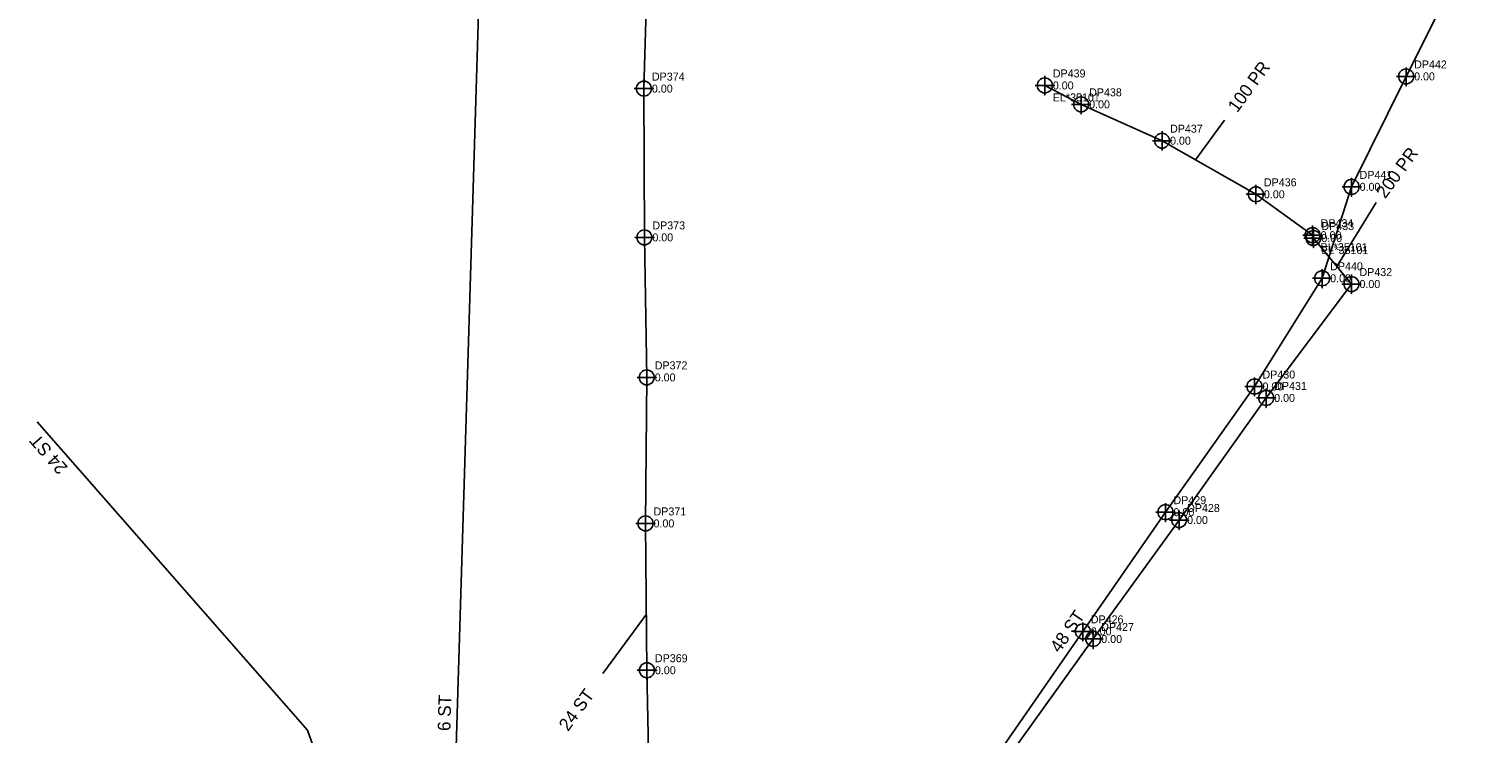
# Model space of a CAD drawing. Extents: x 1182504 to 1186036, y 573002 to 575111.
# Drawn here: x 1183688.1 to 1184140, y 573350.5 to 573570.7 of the extents above; entities that cross this region are included whole.
import ezdxf

# ---------------------------------------------------------------- set-up
doc = ezdxf.new("R2010")
doc.units = 0
for name, color, linetype in [('Exist Utilities Telephone UG Cable SUE LOS C', 7, 'Continuous'), ('Exist Utilities Telephone UG Cable SUE LOS C Cogo Comment', 7, 'Continuous'), ('Exist Utilities Telephone UG Cable SUE LOS C Cogo Elevation', 7, 'Continuous'), ('Exist Utilities Telephone UG Cable SUE LOS C Cogo Number', 7, 'Continuous'), ('Exist Utilities Telephone UG Cable SUE LOS C Cogo Point CELL', 7, 'Continuous'), ('Exist Utilities Telephone UG Cable SUE LOS C Leader', 7, 'Continuous'), ('Exist Utilities Telephone UG Cable SUE LOS C Text', 7, 'Continuous'), ('Exist Utilities Telephone UG Conduit SUE LOS B', 7, 'Continuous'), ('Exist Utilities Telephone UG Conduit SUE LOS B Cogo Elevation', 7, 'Continuous'), ('Exist Utilities Telephone UG Conduit SUE LOS B Cogo Number', 7, 'Continuous'), ('Exist Utilities Telephone UG Conduit SUE LOS B Cogo Point CELL', 7, 'Continuous'), ('Exist Utilities Telephone UG Conduit SUE LOS B Text', 7, 'Continuous'), ('Exist Utilities Telephone UG FO SUE LOS C', 7, 'Continuous'), ('Exist Utilities Telephone UG FO SUE LOS C Cogo Elevation', 7, 'Continuous'), ('Exist Utilities Telephone UG FO SUE LOS C Cogo Number', 7, 'Continuous'), ('Exist Utilities Telephone UG FO SUE LOS C Cogo Point CELL', 7, 'Continuous'), ('Exist Utilities Telephone UG FO SUE LOS C Leader', 7, 'Continuous'), ('Exist Utilities Telephone UG FO SUE LOS C Text', 7, 'Continuous')]:
    doc.layers.add(name, color=color, linetype=linetype)

msp = doc.modelspace()

# ---------------------------------------------------------------- linework, layer by layer
at = {"layer": 'Exist Utilities Telephone UG Cable SUE LOS C'}
for points in [[(1184089.19, 573506.18), (1184071.47, 573518.96), (1184042.14, 573535.72), (1184016.86, 573547.08), (1184005.51, 573552.99)], [(1183761.25, 573038.53), (1183769.09, 573034.41), (1183772.83, 573037.9), (1183792.84, 573062.44), (1183815.5, 573091.52), (1183842.15, 573128.3), (1183871.65, 573168.11), (1183894.45, 573200.64), (1183915.52, 573231.01), (1183941.95, 573268.28), (1183966.78, 573306.07), (1183979.43, 573323.54), (1183993.99, 573342.83), (1184020.65, 573379.96), (1184047.47, 573417.15), (1184074.68, 573455.3), (1184101.33, 573490.9), (1184089.43, 573505.28)]]:
    msp.add_lwpolyline(points, dxfattribs=at)
at = {"layer": 'Exist Utilities Telephone UG Cable SUE LOS C Cogo Point CELL'}
for points in [[(1184005.51, 573555.99), (1184005.51, 573549.99), (1184005.51, 573552.99), (1184008.51, 573552.99), (1184002.51, 573552.99)], [(1184016.86, 573550.08), (1184016.86, 573544.08), (1184016.86, 573547.08), (1184019.86, 573547.08), (1184013.86, 573547.08)], [(1184042.14, 573538.72), (1184042.14, 573532.72), (1184042.14, 573535.72), (1184045.14, 573535.72), (1184039.14, 573535.72)], [(1184071.47, 573521.96), (1184071.47, 573515.96), (1184071.47, 573518.96), (1184074.47, 573518.96), (1184068.47, 573518.96)], [(1184089.19, 573509.18), (1184089.19, 573503.18), (1184089.19, 573506.18), (1184092.19, 573506.18), (1184086.19, 573506.18)], [(1184089.43, 573508.28), (1184089.43, 573502.28), (1184089.43, 573505.28), (1184092.43, 573505.28), (1184086.43, 573505.28)], [(1184101.33, 573493.9), (1184101.33, 573487.9), (1184101.33, 573490.9), (1184104.33, 573490.9), (1184098.33, 573490.9)], [(1184074.68, 573458.3), (1184074.68, 573452.3), (1184074.68, 573455.3), (1184077.68, 573455.3), (1184071.68, 573455.3)], [(1184047.47, 573420.15), (1184047.47, 573414.15), (1184047.47, 573417.15), (1184050.47, 573417.15), (1184044.47, 573417.15)], [(1184020.65, 573382.96), (1184020.65, 573376.96), (1184020.65, 573379.96), (1184023.65, 573379.96), (1184017.65, 573379.96)]]:
    msp.add_lwpolyline(points, dxfattribs=at)
for centre in [(1184005.51, 573552.99), (1184016.86, 573547.08), (1184042.14, 573535.72), (1184071.47, 573518.96), (1184089.19, 573506.18), (1184089.43, 573505.28), (1184101.33, 573490.9), (1184074.68, 573455.3), (1184047.47, 573417.15), (1184020.65, 573379.96)]:
    msp.add_circle(centre, 2.34, dxfattribs=at)
at = {"layer": 'Exist Utilities Telephone UG Cable SUE LOS C Leader'}
for p, q in [((1184052.63, 573529.73), (1184061.7, 573542.18)), ((1184096.74, 573496.44), (1184109.1, 573516.44))]:
    msp.add_line(p, q, dxfattribs=at)
at = {"layer": 'Exist Utilities Telephone UG Conduit SUE LOS B'}
msp.add_lwpolyline([(1184020.78, 573306.4), (1183988.14, 573330.66), (1183985.98, 573336.24), (1183991.53, 573344.95), (1184017.37, 573382.34), (1184043.22, 573419.6), (1184071.03, 573458.88), (1184092.18, 573492.71), (1184101.38, 573521.29), (1184118.41, 573555.81), (1184137.37, 573593.76), (1184158.33, 573627.01), (1184186.36, 573674.25), (1184210.73, 573715)], dxfattribs=at)
at = {"layer": 'Exist Utilities Telephone UG Conduit SUE LOS B Cogo Point CELL'}
for points in [[(1184118.39, 573558.62), (1184118.42, 573552.81), (1184118.41, 573555.81), (1184121.42, 573555.81), (1184115.42, 573555.81)], [(1184101.36, 573524.1), (1184101.39, 573518.29), (1184101.38, 573521.29), (1184104.39, 573521.29), (1184098.39, 573521.29)], [(1184092.16, 573495.52), (1184092.19, 573489.71), (1184092.18, 573492.71), (1184095.19, 573492.71), (1184089.19, 573492.71)], [(1184071.02, 573461.7), (1184071.05, 573455.88), (1184071.03, 573458.88), (1184074.05, 573458.88), (1184068.05, 573458.88)], [(1184043.21, 573422.42), (1184043.24, 573416.6), (1184043.22, 573419.6), (1184046.24, 573419.6), (1184040.24, 573419.6)], [(1184017.35, 573385.15), (1184017.38, 573379.34), (1184017.37, 573382.34), (1184020.38, 573382.34), (1184014.38, 573382.34)]]:
    msp.add_lwpolyline(points, dxfattribs=at)
for centre in [(1184118.42, 573555.81), (1184101.39, 573521.29), (1184092.19, 573492.71), (1184071.05, 573458.88), (1184043.24, 573419.6), (1184017.38, 573382.34)]:
    msp.add_circle(centre, 2.34, dxfattribs=at)
at = {"layer": 'Exist Utilities Telephone UG FO SUE LOS C'}
for points in [[(1183831.2, 573051.4), (1183831.99, 573067.67), (1183835.94, 573100.34), (1183843.81, 573135.41), (1183849.42, 573158.28), (1183872.21, 573240.17), (1183881.95, 573271.33), (1183882.59, 573295.88), (1183881.95, 573329.75), (1183881.17, 573370.19), (1183880.74, 573416.08), (1183881.11, 573461.73), (1183880.38, 573505.49), (1183880.23, 573552), (1183881.56, 573597.96), (1183880.77, 573642.04), (1183880.14, 573689.54)], [(1183763.45, 573220.41), (1183819.5, 573277.67), (1183831.72, 573678.52)], [(1183795.03, 573197.57), (1183821.29, 573222.16), (1183775.15, 573351.47), (1183690.62, 573447.81)]]:
    msp.add_lwpolyline(points, dxfattribs=at)
at = {"layer": 'Exist Utilities Telephone UG FO SUE LOS C Cogo Point CELL'}
for points in [[(1183880.23, 573555), (1183880.23, 573549), (1183880.23, 573552), (1183883.23, 573552), (1183877.23, 573552)], [(1183880.38, 573508.49), (1183880.38, 573502.49), (1183880.38, 573505.49), (1183883.38, 573505.49), (1183877.38, 573505.49)], [(1183881.11, 573464.73), (1183881.11, 573458.73), (1183881.11, 573461.73), (1183884.11, 573461.73), (1183878.11, 573461.73)], [(1183880.74, 573419.08), (1183880.74, 573413.08), (1183880.74, 573416.08), (1183883.74, 573416.08), (1183877.74, 573416.08)], [(1183881.17, 573373.19), (1183881.17, 573367.19), (1183881.17, 573370.19), (1183884.17, 573370.19), (1183878.17, 573370.19)]]:
    msp.add_lwpolyline(points, dxfattribs=at)
for centre in [(1183880.23, 573552), (1183880.38, 573505.49), (1183881.11, 573461.73), (1183880.74, 573416.08), (1183881.17, 573370.19)]:
    msp.add_circle(centre, 2.34, dxfattribs=at)
at = {"layer": 'Exist Utilities Telephone UG FO SUE LOS C Leader'}
msp.add_line((1183881.01, 573387.72), (1183867.39, 573369.14), dxfattribs=at)

# ---------------------------------------------------------------- texts
at = {"layer": 'Exist Utilities Telephone UG Cable SUE LOS C Cogo Comment'}
for s, p in [('EL*35101', (1184008.01, 573547.99)), ('BL*35101', (1184091.69, 573501.18)), ('EL*35101', (1184091.93, 573500.28))]:
    msp.add_text(s, height=2.5, dxfattribs=at).set_placement(p)
at = {"layer": 'Exist Utilities Telephone UG Cable SUE LOS C Cogo Elevation'}
for p in [(1184008.01, 573551.74), (1184019.36, 573545.83), (1184044.64, 573534.47), (1184073.97, 573517.71), (1184091.69, 573504.93), (1184091.93, 573504.03), (1184103.83, 573489.65), (1184077.18, 573454.05), (1184049.97, 573415.9), (1184023.15, 573378.71)]:
    msp.add_text('0.00', height=2.5, dxfattribs=at).set_placement(p)
at = {"layer": 'Exist Utilities Telephone UG Cable SUE LOS C Cogo Number'}
for s, p in [('DP439', (1184008.01, 573555.49)), ('DP438', (1184019.36, 573549.58)), ('DP437', (1184044.64, 573538.22)), ('DP436', (1184073.97, 573521.46)), ('DP434', (1184091.69, 573508.68)), ('DP433', (1184091.93, 573507.78)), ('DP432', (1184103.83, 573493.4)), ('DP431', (1184077.18, 573457.8)), ('DP428', (1184049.97, 573419.65)), ('DP427', (1184023.15, 573382.46))]:
    msp.add_text(s, height=2.5, dxfattribs=at).set_placement(p)
at = {"layer": 'Exist Utilities Telephone UG Cable SUE LOS C Text'}
for s, p in [('100 PR', (1184065.63, 573544.26)), ('200 PR', (1184111.9, 573517.37))]:
    msp.add_text(s, height=4, rotation=53.9157, dxfattribs=at).set_placement(p)
at = {"layer": 'Exist Utilities Telephone UG Conduit SUE LOS B Cogo Elevation'}
for p in [(1184120.91, 573554.56), (1184103.88, 573520.04), (1184094.68, 573491.46), (1184073.53, 573457.63), (1184045.72, 573418.35), (1184019.87, 573381.09)]:
    msp.add_text('0.00', height=2.5, dxfattribs=at).set_placement(p)
at = {"layer": 'Exist Utilities Telephone UG Conduit SUE LOS B Cogo Number'}
for s, p in [('DP442', (1184120.91, 573558.31)), ('DP441', (1184103.88, 573523.79)), ('DP440', (1184094.68, 573495.21)), ('DP430', (1184073.53, 573461.38)), ('DP429', (1184045.72, 573422.1)), ('DP426', (1184019.87, 573384.84))]:
    msp.add_text(s, height=2.5, dxfattribs=at).set_placement(p)
at = {"layer": 'Exist Utilities Telephone UG Conduit SUE LOS B Text'}
msp.add_text('48 ST', height=4, rotation=55.3569, dxfattribs=at).set_placement((1184010.11, 573375.36))
at = {"layer": 'Exist Utilities Telephone UG FO SUE LOS C Cogo Elevation'}
for p in [(1183882.73, 573550.75), (1183882.88, 573504.24), (1183883.61, 573460.48), (1183883.24, 573414.83), (1183883.67, 573368.94)]:
    msp.add_text('0.00', height=2.5, dxfattribs=at).set_placement(p)
at = {"layer": 'Exist Utilities Telephone UG FO SUE LOS C Cogo Number'}
for s, p in [('DP374', (1183882.73, 573554.5)), ('DP373', (1183882.88, 573507.99)), ('DP372', (1183883.61, 573464.23)), ('DP371', (1183883.24, 573418.58)), ('DP369', (1183883.67, 573372.69))]:
    msp.add_text(s, height=2.5, dxfattribs=at).set_placement(p)
at = {"layer": 'Exist Utilities Telephone UG FO SUE LOS C Text'}
for s, rotation, p in [('24 ST', 131.2658, (1183700.4, 573433.64)), ('24 ST', 53.9157, (1183856.55, 573350.89)), ('6 ST', 88.2533, (1183819.74, 573351.15))]:
    msp.add_text(s, height=4, rotation=rotation, dxfattribs=at).set_placement(p)

doc.saveas('drawing.dxf')
